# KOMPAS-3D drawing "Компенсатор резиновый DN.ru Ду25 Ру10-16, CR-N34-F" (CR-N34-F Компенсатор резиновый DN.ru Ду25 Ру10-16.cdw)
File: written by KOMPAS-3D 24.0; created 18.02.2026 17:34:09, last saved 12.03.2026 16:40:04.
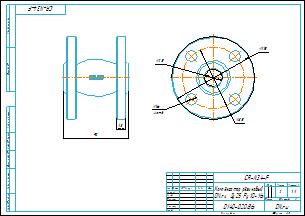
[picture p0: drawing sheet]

Document properties: Типовые: Типовые; Автор: DN.RU; Форматы листов документа: A3; Полное имя файла: CR-N34-F Компенсатор резиновый DN.ru Ду25 Ру10-16.m3d; Масса: 2; Наименование: Компенсатор резиновый DN.ru Ду25 Ру10-16; Количество листов документа: 1; Комментарий: D140-02086; Примечание: D140-02086

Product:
- Body: Твердое тело2  | qty 1
    Масса: 2.463282
- Part/product: Компенсатор резиновый DN.ru Ду25 Ру10-16  | designation CR-N34-F
    Масса: 2
    Раздел спецификации: Прочие изделия
    Форматы листов документа: A3
    Комментарий: D140-02086
    Примечание: D140-02086
    additional columns: Типовые

Views: Вид 1, Спереди, Проекционный вид 2
Referenced files in E:\Работа\Зайцев\CR-N34-F Компенсатор резиновый DN.ru ДУ25-300 Ру10-16\DN25_PN10\: CR-N34-F Компенсатор резиновый DN.ru Ду25 Ру10-16.m3d
Referenced files in E:\Работа\Зайцев\Для компаса\: чертеж DN.ru А3.cdt
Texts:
  CR-N34-F
  чертеж DN.ru А3.cdt
  Компенсатор резиновый
  DN.ru Ду25 Ру10-16
  Твердое тело2
  Компенсатор резиновый DN.ru Ду25 Ру10-16
  CR-N34-F Компенсатор резиновый DN.ru Ду25 Ру10-16
Dimensions and other numbers on the sheet: 0; 3; 2; 4; 90; 13; 115; 85; 25; 16; 4 отв.; 1:1; 1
